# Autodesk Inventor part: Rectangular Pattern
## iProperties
Shininess: 64.0
Length Units: 11269
Angle Units: 11279
Time Units: 11290
Mass Units: 11283
Length Display Precision: 3
Angle Display Precision: 2
Compacted: True
Part Number: Rectangular Pattern
Document SubType Name: Modeling
Created: 2002-12
Designer: deepak
Density: 0.0
Volumn: 0.0
Area: 0.0
PropertySet Name: Model Information
Control State: 0
Master: False
Checked Out: False
Author: deepak
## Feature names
1. Extrusion1
2. Extrusion2
3. Extrusion3
4. Extrusion4
